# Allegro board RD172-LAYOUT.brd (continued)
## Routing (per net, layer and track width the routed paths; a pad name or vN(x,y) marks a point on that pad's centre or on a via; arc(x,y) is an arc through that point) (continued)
GND_5VAC: length 38.2
  TOP w0.2: 130,51.8 130.87,51.8
  TOP w0.25: 122.23,47 120.97,47 ; 120.63,47 v1(119.5,47)
  TOP w0.45: C82.2 130,51.8
  TOP w0.5: 113.8,45.59 113.8,45.11 113.19,44.5 IC15.4 ; 130.2,53.48 130.2,54.52 ; 130.47,54.8 v2(131.8,54.8) 131.8,54 132.7,53.1 TP55.1 ; 113.8,45.82 v2(113.8,47)
  TOP w0.6: C80.2 131,52.4 131,51.8 ; 131,51.8 131,45.54 PS10.5 ; 131,51.8 130.87,51.8
  TOP w0.8: 130.47,54.8 C81.2 130.2,54.52 ; R86.1 122.23,47 ; 120.63,47 C85.2 120.97,47 ; 113.8,45.82 R97.2 113.8,45.59 ; C80.2 130.2,53.48
  CONDUCTIVE2 w1: PS10.5 126.7,43.04 ; PS10.5 130.3,43.04 ; PS10.5 128.5,44.84
  BOTTOM w1.5: PS10.5 130.65,43.04 ; PS10.5 126.35,43.04 ; PS10.5 128.5,45.19
  vias: v2(108.1,48.4)
GND_5VDC: length 45.3
  TOP w0.2: 279.2,43.9 279.2,43.02
  TOP w0.25: v2(247.3,42.35) 247.2,43.3 247.2,44.33
  TOP w0.3: R111.2 262.7,43.85 262.4,43.55 v2(261.9,42.8)
  TOP w0.4: C96.2 261.2,43.1 261.35,43.04 v2(261.9,42.8)
  TOP w0.45: C103.2 279.2,43.9
  TOP w0.5: 249.15,42.35 v2(247.3,42.35) ; 279.2,43.02 279.2,42.9 ; 279.2,42.9 278.5,42.9 C102.2 ; 279.2,42.9 282.6,42.9 PS11.5 291.7,42.04 292,42.34 292,43.42 ; 277.32,43.8 276.27,43.8 ; IC16.4 v2(261.9,42.8) ; 276,43.52 v2(276,42.2) ; 292.27,43.7 296.2,43.7 TP64.1 ; 275.73,43.8 274.68,43.8
  TOP w0.8: 276.27,43.8 C101.2 ; C101.2 275.73,43.8 ; C101.2 276,43.52 ; C102.2 277.32,43.8 ; 274.68,43.8 C90.2 ; 292,43.42 R129.1 292.27,43.7 ; 247.2,44.33 R127.2
  TOP w1.5: IC18.4 249.15,42.35
  BOTTOM w1: PS11.5 285.4,42.04 ; PS11.5 281.6,42.04 ; PS11.5 283.5,43.94
GND_24V: length 109.4
  TOP w0.5: TP53.1 88.6,9.5 ; TP53.1 90.2,7.55 ; TP53.1 90.2,11.45 ; TP53.1 91.8,9.5 ; 69.6,16.65 C10.2 68.2,15.5 ; v2(103.9,158.8) 104.3,159.2 ; 104.3,159.2 C4.2 ; 104.3,159.2 104.25,159.2 ; C76.2 92.5,13.8 ; C76.2 88.2,13.8 ; C76.2 v2(90.2,11.9) ; TP9.1 116.7,159.5 ; TP9.1 118.3,157.55 ; TP9.1 118.3,161.45 ; 91.91,161.55 v2(90.8,161.55) ; C4.2 105.4,160.35 ; C4.2 105.4,158.05 ; LED1.C 71.2,9.65 ; 97.57,161.5 v2(98.8,161.5)
  TOP w0.6: 85.3,9.4 83.5,9.4 ; 83.5,9.4 83.5,7.8 ; 83.5,9.4 81.5,9.4 ; 83.5,9.4 C11.2 ; ZD1.A 79.4,10.85 ; ZD1.A 74.7,10.85 ; ZD1.A 76.9,8.8
  TOP w0.8: Q2.S 91.91,161.55 ; v2(130,157) 129.4,156.4 129.4,155.65 ; R17.1 97.57,161.5
  TOP w1: C50.2 129.4,152.82 130.02,152.2 PS7.2 ; PS3.2 234.19,34.9 231.17,34.9 ; PS1.3 79.46,37.25 ; PS1.3 81.61,35.1 ; PS1.3 79.46,32.95 ; PS1.3 77.31,35.1 ; C17.2 v2(227.7,34.9)
  TOP w1.2: C50.2 129.4,155.65 ; C17.2 231.17,34.9
  CONDUCTIVE2 w0.8: PS1.3 81.41,35.1 ; PS1.3 79.46,37.05 ; PS1.3 79.46,33.15 ; PS1.3 77.51,35.1
  CONDUCTIVE2 w1: PS5.2 141,35.42 ; PS5.2 142.5,34.2 ; PS5.2 144.5,35.42 ; PS9.-VIN 103.7,14.11 ; PS9.-VIN 102,12.41 ; PS9.-VIN 100.3,14.11 ; PS9.-VIN 102,15.31
  CONDUCTIVE2 w1.5: 236.95,35.42 PS3.2 233.05,35.42
  BOTTOM w1: 236.8,35.42 PS3.2 233.2,35.42 ; 130.02,151.4 PS7.2 130.02,147.8 ; PS1.3 79.46,37.25 ; 144.3,35.42 PS5.2 140.7,35.42
  BOTTOM w1.5: PS1.3 79.46,32.7 ; PS1.3 81.86,35.1 ; PS1.3 77.06,35.1
  vias: v2(4.9,143.8) v2(5,100.5) v2(5,68.6) v2(5.4,32) v2(34.8,5.6) v2(38.5,158.8) v2(53.3,17.6) v2(62.7,6.7) v2(69.1,17.1) v2(71.34,8.9) v2(76.87,8.57) v2(77.8,159.1) v2(80.4,157) v2(80.5,161.2) v2(83.5,7.72) v2(90.24,7.08) v2(111.5,11.5) v2(111.5,9) v2(111.5,6.5) v2(111.5,4) v2(116,161) v2(117.3,155.1) v2(138,28.5) v2(139,29.5) v2(139,27.4)
GND_M: length 132.6
  TOP w0.25: D20.A 203.6,142.5 203.3,142.2 203.3,141.3 203.6,141 204.08,141 ; 182.84,142.8 182.2,142.8 182,142.6 182,141.9 182.5,141.4 182.98,141.4
  TOP w0.5: 208.94,147.11 208.94,146.66 v2(209.6,146) 209.6,145.2 209.9,144.9 ; IC10.8 189.52,147.75 ; IC10.8 188.44,149.47 ; IC10.8 188.44,146.03 ; 148,144.75 C51.2 146,146.1 ; 200.06,149.47 IC12.1 198.98,147.75 ; 179.56,146.85 v2(179.56,146.1) 179.56,146.03 ; 162.35,148.1 C53.2 161.2,149.25 ; 200.06,146.85 v2(200.06,146.1) 200.06,146.03 ; IC10.3 182.09,149.47 ; C52.2 151.5,144.55 ; 203.4,137.1 R74.2 C68.1 ; 203.4,137.1 203.58,137.2 v2(204.1,137.5) v2(204.1,139.5) 204.2,140.09 204.2,140.72 ; 203.4,137.1 203.95,137.1 ; 202.59,146.89 v2(202.59,145.95) 202.59,145.31 203.4,144.5 C67.2 203.6,145.65 ; 183,141.13 v2(183,139.9) ; 209.9,144.9 C66.2 211.25,143.5 ; 209.9,144.9 209.9,145.5 ; 183.1,136.6 182.2,135.7 C59.2 R67.1 182.85,137.3 ; C58.2 182.09,145.31 v2(182.09,145.9) 182.09,146.87 ; 178.48,147.75 IC10.1 179.56,149.47 ; C68.1 202.9,135.7 203.7,135.7 204.1,136.1 v2(204.1,136.3) ; C68.1 202.8,134.45 ; IC12.3 202.59,149.47 ; 210.02,147.75 IC12.8 208.94,149.47 ; 190.2,143.7 C57.2 189.1,145.7 ; D18.A 182.84,142.8 ; R60.1 153.1,143.8
  TOP w0.6: IC12.3 202.59,146.89 ; IC12.8 208.94,147.11 ; IC9.3 161.5,149.63 ; IC12.1 200.06,146.85 ; IC9.4 161.5,150.91 ; IC10.3 182.09,146.87 ; IC10.1 179.56,146.85
  TOP w0.8: 204.2,140.72 C69.2 204.08,141 ; 182.98,141.4 C60.2 183,141.13
  TOP w1: 213.65,134.9 212.45,133.7 Q8.S ; Q8.S 212.45,131.1 ; Q8.S 214.6,133 ; 137.64,151.4 PS7.5 137.64,147.8 ; 192.4,135.05 190.95,133.6 Q7.S ; Q7.S 193.1,133 ; Q7.S 190.95,131.2
  CONDUCTIVE2 w1: 137.64,151.3 PS7.5 137.64,147.9 ; Q8.S 212.45,135.05 ; Q8.S 212.45,130.95 ; Q8.S 214.5,133 ; Q8.S 210.4,133 ; Q7.S 190.95,130.95 ; Q7.S 190.95,135.05 ; Q7.S 193,133 ; Q7.S 188.9,133
  BOTTOM w0.5: 197.75,139.35 CN6.G1 199.55,137.8 ; 179.05,135.7 CN5.G1 177.25,137.25 ; CN5.G2 173.75,134.15 ; CN5.G2 173.75,137.25 ; CN5.G2 171.95,135.7 ; TP37.1 195,142.95 ; TP37.1 196.6,141 ; TP37.1 193.4,141
  BOTTOM w1: 137.64,147.8 PS7.5 137.64,151.4
  BOTTOM w1.5: Q7.S 188.8,135.15
  vias: v2(146,144.1) v2(147.7,150.9) v2(151.5,144.1) v2(152,150) v2(161.5,149.5) v2(162,136) v2(162.1,138.6) v2(175,148.5) v2(183.1,138.5) v2(183.3,137.2) v2(189.1,146.05) v2(192.5,149) v2(211.5,149.5) v2(215,140) v2(215.5,131.5) v3(175.5,136.5) v3(196,138.6)
GND_N: length 129.8
  TOP w0.2: 177.4,54.9 178.6,54.9
  TOP w0.4: C39.2 177.3,56.6
  TOP w0.5: C42.2 164.95,49 ; C42.2 163.8,47.85 ; C42.2 163.8,50.15 ; 166.4,59.4 R49.2 C43.1 ; IC7.3 163.41,47.47 ; 154.92,61.3 IC6.4 156.63,62.38 ; 158.1,60.34 159,60.34 ; 158.1,60.34 158.1,61.3 ; 158.1,60.34 157.8,60.03 157.28,60.03 ; 159,60.34 v2(159,61.3) 158.1,61.3 ; 159,60.34 C38.2 160.2,59.2 ; 157.53,61.3 158.1,61.3 ; 184.41,46.39 184.41,46.9 v2(184.5,47.6) 184.5,48.78 ; IC5.3 184.41,44.02 ; 165.94,47.47 IC7.1 167.02,45.74 ; C43.1 168,62.2 ; C43.1 v2(166.5,61) ; C41.2 157.6,51.8 ; C41.2 156.25,49.8 ; C41.2 157.6,48.8 v2(156.42,47.68) 157.06,47 157.06,46.39 ; 146.22,56.2 v2(147.4,56.2) ; C36.2 145.4,55 ; C36.2 145.4,51 ; C36.2 146.75,53 ; C37.2 146,55.05 ; IC5.1 186.94,43.8 ; R46.1 155.35,63.2 ; R46.1 154.2,64.35 ; R46.1 154.2,62.05 ; 186.94,46.64 v1(186.94,47.3) 186.94,47.47 ; 178.06,44.02 IC5.8 178.06,47.47 ; v1(187,62.3) 186.5,61.8 C34.2 R42.1 v2(186.5,58.7) ; C32.2 176.95,49.8 ; C32.2 178.3,48.3 177.6,47.6 ; C32.2 178.3,51.8 ; IC7.2 164.68,47.47 ; 178.6,54.9 D13.A ; IC7.8 155.98,45.74
  TOP w0.6: IC5.3 184.41,46.39 ; C33.2 184.5,50.1 ; IC7.8 157.06,46.39 ; IC5.1 186.94,46.64 ; IC6.3 157.28,60.03 ; IC6.4 157.53,61.3
  TOP w0.7: Q6.S2 166.87,62.2 ; Q6.S1 165.59,62.1 ; Q6.S3 168.13,62.2
  TOP w0.8: C33.2 184.5,48.78 ; C37.2 146.22,56.2
  TOP w1: v2(166.5,59.5) 166.5,56.5 ; Q5.S 178.05,62.85 ; Q5.S 178.05,66.4 ; Q5.S 175.9,64.5 ; 140.7,43.04 141.1,43.04
  TOP w1.5: 144.55,43.04 PS5.5 141.1,43.04
  CONDUCTIVE2 w1: Q5.S 178.05,66.55 ; Q5.S 176,64.5 ; Q5.S 180.1,64.5 ; Q5.S 178.05,62.45 ; PS5.5 141.3,43.04 ; PS5.5 142.5,44.24 ; PS5.5 144.2,43.04
  BOTTOM w0.5: TP28.1 155.4,62.9 ; TP28.1 157,60.95 ; TP28.1 157,64.85 ; TP28.1 158.6,62.9 ; CN3.G1 180.25,57.2 ; 179.25,59.4 CN4.G2 177.45,57.85 ; CN4.G1 173.95,57.85
  BOTTOM w1: 144.6,43.04 PS5.5 140.7,43.04 ; Q5.S 178.05,66.9 ; Q5.S 180.3,64.5 ; Q5.S 175.8,64.5 ; Q5.S 178.05,62.4
  vias: v1(176.5,55.4) v2(162.5,63.3) v2(162.5,61.9) v2(162.5,60.5) v2(162.5,59.1) v2(164,60.1) v2(164.1,63.3) v2(164.1,61.8) v2(164.68,47.6) v2(164.8,59) v2(165.2,60.8) v2(165.9,56.5) v2(175.7,51.2) v2(175.75,53.75) v2(177.7,47.6) v3(175.7,58.6) v3(183.8,56.4)
GND_P: length 128.3
  TOP w0.2: 206.5,55.1 207.82,55.1
  TOP w0.5: v2(203.3,47.9) 203.6,48.5 C15.2 ; IC3.1 202.02,45.74 ; IC3.1 200.94,47.47 ; IC3.1 200.94,44.02 ; 203.56,44.02 IC1.8 202.48,45.74 ; 209.91,46.65 v2(209.91,47.6) 209.9,48.9 209.8,49 209.8,49.98 ; 198.41,47.8 IC3.3 198.41,44.02 ; 199,66.15 C26.1 197.85,65 ; 207.82,55.1 D8.A ; Q4.S1 195.37,68.03 ; C24.2 194.1,53.5 ; C24.2 192.9,51.5 ; C24.2 194.1,49.5 ; C18.2 230.5,42.25 ; C18.2 228.5,43.6 ; C18.2 232.5,43.6 ; C20.2 205.2,56.7 v3(205,56.9) ; 225.7,56.55 C21.2 v2(221.69,55.4) 221.69,54.3 ; C15.2 202.25,50.5 ; C15.2 203.6,52.5 ; 197.8,47.6 C25.2 198.95,49 ; 227.6,43.55 C19.2 228.5,44.7 ; 215.8,60.92 215.8,59.88 ; 212.44,47.47 v1(212.44,47.3) IC1.1 ; 199.68,47.9 IC3.2 199.68,44.02 ; C22.2 215.8,61.7 v2(216.2,62.5) ; IC1.3 209.91,44.02 ; IC2.3 225.06,51.62 ; IC2.4 223.79,51.62 ; IC2.4 222.72,53.34 ; IC2.4 223.79,55.05 ; R30.2 197.85,63.5 ; 224.85,44.7 R27.1 226,43.55 ; C16.2 209.8,51.15 ; 215.8,59.58 215.8,58.6
  TOP w0.6: v2(191.9,47.7) 192.06,46.9 IC3.8 ; v2(203.3,47.9) 203.56,47.65 IC1.8 ; IC1.3 209.91,46.65
  TOP w0.7: Q4.S1 196.5,66.4 ; Q4.S3 199.03,66.4 ; 197.76,68.03 197.76,66.2
  TOP w0.8: 215.8,59.88 R26.1 215.8,59.58 ; C16.2 209.8,49.98 ; C22.2 215.8,60.92
  TOP w1: Q3.S 207.05,62.6 ; v2(196.7,59.7) v2(196.7,62.6)
  TOP w1.5: 233.3,43.04 PS3.5 237.05,43.04
  CONDUCTIVE2 w1: Q3.S 207.05,66.55 ; Q3.S 209.1,64.5 ; Q3.S 207.05,62.45 ; Q3.S 205,64.5 ; PS3.5 233.3,43.04 ; PS3.5 236.7,43.04 ; PS3.5 235,44.24
  BOTTOM w0.5: 222.3,56.95 CN1.G1 223.85,58.75 ; 206.75,59.25 CN2.G2 208.55,57.7 ; CN1.G2 223.85,62.25
  BOTTOM w0.7: 207,72.25 207,75.07
  BOTTOM w1: Q3.S 207.05,67.1 ; Q3.S 207.05,62.25 ; Q3.S 204.8,64.5 ; Q3.S 209.3,64.5
  BOTTOM w1.5: 232.9,43.04 PS3.5 236.7,43.04
  BOTTOM w1.7: 207,75.07 TP19.1
  vias: v2(194.4,67.8) v2(194.5,66.3) v2(195.7,65.5) v2(195.9,64) v2(196.8,66.4) v2(197.6,65.1) v2(197.6,63.5) v2(198.4,66.4) v2(199.7,47.7) v2(215.2,58.3) v2(227.7,42.2) v3(223.1,60.5)
/DI0_BO: length 40.6
  TOP w0.2: 236.25,6.02 236.25,4.73 v1(236.4,4.4) ; v1(236.4,14.7) 236,15.1 230.45,15.1 229.25,16.3 216.7,16.3 215.6,17.4 209.95,17.4
  TOP w0.25: CN8.51 236.25,6.02
  TOP w0.8: 209.95,17.4 R139.2
  BOTTOM w0.2: v1(236.4,4.4) v1(236.4,14.7)
/DI1_BO: length 25.2
  TOP w0.2: 236.25,11.98 236.25,13.35 234.95,14.65 230.26,14.65 229.11,15.8 216.2,15.8 215.6,16.4 214.75,16.4
  TOP w0.25: CN8.52 236.25,11.98
  TOP w0.8: 214.75,16.4 R140.2
/DO1_BI: length 66.4
  TOP w0.2: v1(237.9,15.3) 245.7,15.3 251.2,9.8 264.04,9.8 274.24,20 285.55,20 ; 287.57,17.27 286.85,17.27 285.7,18.43 285.7,19.85 ; 233.75,11.98 v1(233.75,12.8)
  TOP w0.25: CN8.42 233.75,11.98
  TOP w0.35: IC20.2 287.57,17.27
  TOP w0.8: 285.55,20 R141.1 285.7,19.85
  BOTTOM w0.2: v1(237.9,15.3) 237.6,15.5 235.4,15.5 233.75,13.85 v1(233.75,12.8)
/DO3_BI: length 75.4
  TOP w0.2: v1(183.8,15.3) 228.97,15.3 230.07,14.2 233.6,14.2 234.4,13.4 234.4,12.5 234.25,12.35 234.25,11.98 ; 186.57,18.68 v1(183.8,18.68) 183.22,18.68 181.9,17.35 181.9,16.55 181.1,15.75 178.05,15.75 177.7,16.1 177.7,20 176.1,21.6 175.35,21.6
  TOP w0.25: 234.25,11.98 CN8.44
  TOP w0.35: IC19.6 186.57,18.68
  TOP w0.8: 175.35,21.6 R133.1
  BOTTOM w0.2: v1(183.8,15.3) v1(183.8,18.68)
/FLT: length 510
  TOP w0.2: 195.25,28.55 195.25,28.35 ; 195.25,28.55 195.05,28.35 ; 195.25,28.55 195.45,28.35 ; 195.25,28.55 195.25,32.35 197.13,34.23 197.13,35.48 ; 195.25,28.35 195.05,28.35 ; 195.25,28.35 195.45,28.35 ; 183.55,28.35 183.75,28.35 ; 183.55,28.35 170.35,28.35 170.3,28.4 v1(170,28.6) 169.7,28.4 169.65,28.35 163.25,28.35 162.74,28.86 162.74,32.1 162.13,32.7 162.13,35.48 ; 183.55,28.35 183.75,28.55 ; 183.75,28.35 183.75,28.55 ; 183.75,28.35 183.95,28.35 ; 183.37,158.02 v1(183.37,159.5) ; 170.5,20.77 170.5,19.3 171.3,18.5 171.3,15 172.2,14.1 174.9,14.1 175.2,14.4 175.2,15.05 ; 183.75,28.55 183.75,34.15 183.13,34.77 183.13,35.48 ; 183.75,28.55 183.95,28.35 ; 195.05,28.35 183.95,28.35 ; 175.29,16.8 176.35,16.8 176.7,16.45 176.7,15.5 177.25,14.95 181.75,14.95 184.18,17.38 186.57,17.38 ; 195.45,28.35 207.23,28.35 v1(207.8,28.92) 207.8,34.1 208.63,34.94 208.63,35.48 ; v1(208.4,22.8) 222.49,22.8 226.54,18.75 246.79,18.75 253.94,11.6 263.01,11.6 275.26,23.85 290.56,23.85 295,28.29 v1(295,29.5) ; v1(203.87,159.25) 203.87,158.02
  TOP w0.3: v1(170.5,22.6) 170.5,21.25 ; 175.2,16.61 175.2,15.39
  TOP w0.6: 203.87,158.02 IC12.13 ; 162.13,35.48 IC7.13 ; 183.13,35.48 IC5.13 ; IC10.13 183.37,158.02 ; 208.63,35.48 IC1.13 ; IC3.13 197.13,35.48
  TOP w0.8: 175.2,15.39 R135.1 175.2,15.05 ; 175.29,16.8 C108.1 175.2,16.61
  TOP w1.7: 170.5,21.25 TP67.1 170.5,20.77
  BOTTOM w0.2: v1(295,29.5) 295,31.79 305.3,42.09 305.3,112.55 310.45,117.7 318.41,117.7 323.8,123.09 323.8,152.71 314.56,161.95 218.95,161.95 215.6,158.6 204.51,158.6 v1(203.87,159.25) 203.57,159.45 202.25,159.45 201.55,158.75 184.12,158.75 v1(183.37,159.5) ; v1(170,28.6) 170.5,28.1 v1(170.5,22.6) ; v1(207.8,28.92) 207.8,23.4 v1(208.4,22.8)
/MAINRLY_24V: length 23.8
  TOP w0.5: 100.33,159.4 94.4,159.4 94.35,159.45 93.07,159.45 ; 85,160.15 85,156.35 85.6,155.75 RLY2.1 89.62,156.92 92.15,159.45 92.72,159.45 ; 100.65,161.12 100.65,160.4 100.6,159.93
  TOP w0.8: 92.72,159.45 Q2.D 93.07,159.45 ; 100.6,159.93 R12.2 100.33,159.4 ; 100.65,161.12 D2.A
  TOP w1.7: 85,160.15 TP11.1
/PWM1A_BI: length 69.5
  TOP w0.2: 229.75,6.02 229.75,5.45 230.2,5 230.2,3.85 228.9,2.55 223.85,2.55 216.95,9.45 v1(186.5,9.45) ; 180.55,21.6 181.5,21.6 181.8,21.3 v1(185.35,21.3) 185.71,21.27 186.57,21.27
  TOP w0.25: 229.75,6.02 CN8.25
  TOP w0.35: IC19.2 186.57,21.27
  TOP w0.8: 180.55,21.6 R136.1
  BOTTOM w0.2: v1(186.5,9.45) 186.5,20.15 v1(185.35,21.3)
/PWM1B_BI: length 63.8
  TOP w0.2: 186.57,20.62 182.07,20.62 v1(181.7,20.25) 181.45,20 180.55,20 ; 229.75,11.98 229.75,13.25 228.7,14.3 184.6,14.3 184.3,14 182.1,14 182,14.1 v1(181.7,14.3)
  TOP w0.25: 229.75,11.98 CN8.26
  TOP w0.35: IC19.3 186.57,20.62
  TOP w0.8: 180.55,20 R130.1
  BOTTOM w0.2: v1(181.7,20.25) v1(181.7,14.3)
/PWM2A_BI: length 71.7
  TOP w0.2: 230.25,6.02 230.25,5.65 230.7,5.2 230.7,3.65 229.15,2.1 223.4,2.1 217,8.5 186.1,8.5 185.6,9 v1(184.45,9) ; 186.57,19.98 v1(184,19.98) 182.57,19.98 181,18.4 180.55,18.4
  TOP w0.25: 230.25,6.02 CN8.27
  TOP w0.35: IC19.4 186.57,19.98
  TOP w0.8: 180.55,18.4 R131.1
  BOTTOM w0.2: v1(184.45,9) 184.45,19.52 v1(184,19.98)
/PWM2B_BI: length 63.3
  TOP w0.2: 230.25,11.98 230.25,13.39 228.84,14.8 184.4,14.8 184.2,14.6 183.36,14.6 v1(183,14.65) ; 180.55,16.8 181.2,16.8 181.45,17.05 181.45,17.85 v1(182.85,19.25) 183.45,19.32 186.57,19.32
  TOP w0.25: CN8.28 230.25,11.98
  TOP w0.35: IC19.5 186.57,19.32
  TOP w0.8: 180.55,16.8 R132.1
  BOTTOM w0.2: v1(183,14.65) 183,16.15 183.3,16.45 183.3,17.95 182.85,18.4 v1(182.85,19.25)
/PWM_MA: length 407.1
  TOP w0.2: 193.72,161.5 195.7,161.5 197.6,163.4 211.2,163.4 211.7,162.9 211.7,160.4 212.1,160 219.5,160 221.2,161.7 314.03,161.7 323.2,152.53 323.2,123.2 318.2,118.2 310.2,118.2 305.2,113.2 305.2,37.08 291.07,22.95 275.77,22.95 263.52,10.7 251.64,10.7 245.84,16.5 231.03,16.5 229.73,17.8 217.3,17.8 215.6,19.5 207,19.5 206.2,18.7 196.1,18.7 194.82,19.98 193.43,19.98 ; 185.5,160.05 185.5,159.16 185.91,158.75 185.91,157.96 ; 185.52,160.2 186,160.2 186.5,160.7 186.5,162.6 186.8,162.9 190.1,162.9 191.5,161.5 TP69.1
  TOP w0.35: IC19.17 193.43,19.98
  TOP w0.6: IC10.11 185.91,157.96
  TOP w0.8: 185.5,160.05 R62.1 185.52,160.2
  TOP w1.7: 193.72,161.5 TP69.1
/PWM_MB: length 385.8
  TOP w0.2: v1(205.1,160.4) 205.45,160.33 205.67,160.33 206.08,159.92 R72.1 ; 213.72,161.5 v1(215.7,161.5) 220.1,161.5 220.8,162.2 314.16,162.2 323.8,152.56 323.8,123.09 318.41,117.7 310.41,117.7 305.7,112.99 305.7,36.87 291.33,22.5 276.03,22.5 263.78,10.25 251.39,10.25 245.64,16 230.82,16 229.52,17.3 217.1,17.3 215.4,19 207.2,19 206.4,18.2 195.9,18.2 194.78,19.32 193.43,19.32 ; 206.41,157.99 206.41,158.8 206.5,158.9 206.5,159.55
  TOP w0.35: 193.43,19.32 IC19.16
  TOP w0.6: IC12.11 206.41,157.99
  TOP w0.8: 206.5,159.55 R72.1
  TOP w1.7: 213.72,161.5 TP70.1
  BOTTOM w0.2: v1(205.1,160.4) 206.75,161.5 v1(215.7,161.5)
/PWM_N: length 124.6
  TOP w0.2: R38.1 181.95,31.7 182.45,31.2 v1(182.45,29.55) ; 241.97,14 238,14 236.45,15.55 230.63,15.55 229.38,16.8 216.9,16.8 215.2,18.5 207.38,18.5 206.57,17.7 198.75,17.7 v1(198.53,17.48) 195.93,17.48 194.72,18.68 193.43,18.68 ; v1(161.2,29.9) 161.2,31.3 160.6,31.9 159.62,31.9 ; R47.1 159.59,32.6 159.59,35.48 ; v1(198.98,24.14) 198.5,24.3 185.3,24.3 184.6,23.6 v1(182.2,23.6) 181.9,23.9 162.8,23.9 162.5,24.2 v1(161.2,24.2) ; 180.59,35.48 180.59,33.05 181.2,32.45 181.2,31.85
  TOP w0.35: IC19.15 193.43,18.68
  TOP w0.6: IC7.11 159.59,35.48 ; IC5.11 180.59,35.48
  TOP w0.8: 181.2,31.85 R38.1 ; R47.1 159.62,31.9
  TOP w1.7: 241.97,14 TP71.1
  BOTTOM w0.2: v1(161.2,29.9) v1(161.2,24.2) ; v1(182.2,23.6) 182.2,29.3 v1(182.45,29.55) ; v1(198.53,17.48) 198.98,17.93 v1(198.98,24.14)
/PWM_P: length 48.9
  TOP w0.2: v1(206.2,30.45) 206.2,31.35 205.85,31.7 R19.1 ; 192.38,20.62 191.7,20.62 191.4,20.93 191.4,22.6 191.7,22.9 v1(192.8,22.9) 194.5,22.9 194.9,23.3 198.1,23.3 199.4,22 201.18,22 ; 192.8,31.85 192.8,32.69 194.59,34.48 194.59,35.48 ; R28.1 193.6,31.7 193.95,31.35 v1(193.95,29.6) ; v1(203.8,22) 201.62,22
  TOP w0.25: 206.09,35.46 206.09,33.9 204.9,32.7 204.9,31.87
  TOP w0.35: IC19.18 192.38,20.62
  TOP w0.6: IC3.11 194.59,35.48 ; IC1.11 206.09,35.46
  TOP w0.8: 204.9,31.87 R19.1 ; 192.8,31.85 R28.1
  TOP w1.7: 201.18,22 TP68.1 201.62,22
  BOTTOM w0.2: v1(193.95,29.6) 193.95,25.05 192.8,23.9 v1(192.8,22.9) ; v1(206.2,30.45) 206.2,24.4 v1(203.8,22)
/RESET: length 502.4
  TOP w0.2: v1(199.55,17) 199.25,16.8 195.9,16.8 194.68,18.02 193.43,18.02 ; v1(294,29.5) 294,28 290.3,24.3 275,24.3 262.75,12.05 254.12,12.05 246.97,19.2 226.8,19.2 222.19,23.8 208.5,23.8 ; 209.91,35.61 209.91,35.01 208.41,33.51 v1(208.41,30.45) ; 182.09,158.02 v1(182.09,158.8) ; 206.32,23.8 204.2,23.8 203.6,24.4 v1(200,24.4) 199.7,24.8 184.6,24.8 v1(184.1,24.3) 183,24.3 182.7,24.6 v1(163.5,24.6) ; v1(163.5,29.1) 163.41,29.7 163.41,35.48 ; v1(195.91,30.45) 198.41,32.95 198.41,35.48 ; 184.41,35.48 v1(184.41,30.3) ; v1(202.59,158.8) 202.59,158.02 ; v1(208.5,23.8) 206.62,23.8
  TOP w0.35: 193.43,18.02 IC19.14
  TOP w0.6: 202.59,158.02 IC12.14 ; IC10.14 182.09,158.02 ; IC5.14 184.41,35.48 ; IC1.14 209.91,35.61 ; IC7.14 163.41,35.48 ; IC3.14 198.41,35.48
  TOP w1.7: 206.32,23.8 TP72.1 206.62,23.8
  BOTTOM w0.2: v1(195.91,30.45) 195.91,26.09 196.5,25.5 198.9,25.5 v1(200,24.4) 199.55,23.95 v1(199.55,17) ; v1(182.09,158.8) 182.6,158.29 202.09,158.29 v1(202.59,158.8) 203.9,157.5 217.5,157.5 221.5,161.5 314.3,161.5 323.3,152.5 323.3,123.3 318.2,118.2 310.2,118.2 304.8,112.8 304.8,42.3 294,31.5 v1(294,29.5) ; v1(208.41,30.45) 208.41,29.6 208.5,29.5 v1(208.5,23.8) ; v1(163.5,29.1) v1(163.5,24.6) ; v1(184.1,24.3) 184.1,30 v1(184.41,30.3)
AC_L: length 101.5
  TOP w1: RLY2.3 117.1,143.75 117.69,143.84 TP2.1
  CONDUCTIVE2 w1: R5.2 116.5,120.2 ; R5.2 118.3,122 ; R5.2 116.5,123.8 ; R5.2 114.7,122 ; R4.2 114.7,133 ; R4.2 118.3,133 ; R4.2 116.5,134.8 ; R4.2 116.5,131.2 ; 152.6,138.15 151.5,139.25 C6.1 ; D7.A 162.56,122.43 ; D7.A 164.46,120.4 ; D7.A 164.46,124.6 ; C7.1 129.2,139.25 ; C7.1 131,140.9 ; C7.1 132.8,139.25 ; C7.1 131,137.45 ; 162.56,113.57 D12.C 164.46,115.47 ; C6.1 149.2,139.25 ; C6.1 151,137.45
  CONDUCTIVE2 w1.5: RLY2.3 114.8,141.5 ; RLY2.3 117.05,143.75 ; RLY2.3 114.8,145.5 ; RLY2.3 112.55,143.75
  BOTTOM w1: R4.2 115,133 ; R4.2 116.5,131.1 ; R4.2 118.4,133 ; R4.2 116.5,134.9 ; 153.4,137.95 153.4,138.3 152.45,139.25 C6.1 ; 164.46,124.03 D7.A 164.46,120.4 ; 164.46,111.47 D12.C 164.46,115.2 ; R5.2 116.5,120.1 ; R5.2 116.5,123.9 ; R5.2 118.4,122 ; R5.2 115,122 ; C7.1 131,141
  BOTTOM w1.5: RLY2.3 112.45,143.75 ; RLY2.3 114.8,145.6 ; RLY2.3 117.15,143.75 ; RLY2.3 114.8,141.4 ; D12.C 162.5,113.57 ; C7.1 133.5,139.25 ; C7.1 131,136.75 ; C7.1 128.5,139.25 ; 148.5,139.25 C6.1 151,136.75 ; D7.A 162.36,122.43
AC_L_IN: length 132.1
  TOP w0.25: v1(103.9,73.3) 103.9,68.5 R88.1
  TOP w0.5: 40.65,15 39.1,15 33.74,20.36 PS1.2
  TOP w1.7: 40.65,15 TP10.1
  CONDUCTIVE2 w1: R1.1 95.2,133 ; R1.1 97,134.8 ; R1.1 98.8,133 ; R1.1 97,131.2 ; R2.1 97,123.8 ; R2.1 97,120.2 ; R2.1 98.8,122 ; R2.1 95.2,122 ; C3.1 101.25,95.2 ; C3.1 99.45,97 ; C3.1 101.25,98.8 ; C3.1 103.05,97 ; C120.1 65.5,89 ; C120.1 68.7,89 ; C120.1 67,87.3 ; C120.1 67,90.7 ; PS1.2 33.74,26.99 ; PS1.2 33.74,22.89 ; PS1.2 31.69,24.94 ; PS1.2 35.79,24.94
  CONDUCTIVE2 w1.5: RLY2.4 87.2,145.5 ; RLY2.4 89.45,143.75 ; RLY2.4 84.95,143.75 ; RLY2.4 87.2,141.5
  CONDUCTIVE2 w2: L2.2 93.2,124.5
  BOTTOM w1: PS1.2 31.59,24.94 ; PS1.2 33.74,27.09 ; PS1.2 35.89,24.94 ; PS1.2 33.74,22.79 ; C120.1 65.5,89 ; C120.1 67,90.8 ; C120.1 67,87.2 ; C120.1 68.8,89 ; R2.1 97,120.1 ; R2.1 97,123.9 ; R2.1 95.1,122 ; R2.1 98.6,122 ; R1.1 95.1,133 ; R1.1 97,134.9 ; R1.1 98.6,133 ; R1.1 97,131.1 ; C3.1 101.25,99.5 ; C3.1 103.75,97 ; C3.1 98.75,97 ; C3.1 101.25,94.5
  BOTTOM w1.5: RLY2.4 89.55,143.75 ; RLY2.4 84.85,143.75 ; RLY2.4 87.2,145.5 ; RLY2.4 87.2,141.4 ; L2.2 87.5,124.5 ; L2.2 92.65,124.5 ; L2.2 90,127.15 ; L2.2 90,121.85
AC_N: length 95
  TOP w0.25: 116.3,51.56 116.3,52.3 116,52.6 116,53.08 ; 115.83,54.8 v1(114.7,54.8) ; 116.15,51.33 114.72,51.33 114.4,51 114.4,50.37 ; 116,53.37 116,54.63
  TOP w0.45: R100.1 114.4,50.37
  TOP w0.6: 116.3,51.56 L5.2 116.15,51.33
  TOP w0.8: 116,53.37 R94.1 116,53.08 ; 116,54.63 C87.2 115.83,54.8
  CONDUCTIVE2 w0.25: CT1.10 99.85,72.55 108,64.4 108,57.5 109.1,56.4 113.8,56.4 114.7,55.5 v1(114.7,54.8)
  CONDUCTIVE3 w1.2: 97.75,77.29 CT1.9 102.4,77.29 ; CT1.8 101.9,79.83 ; CT1.8 99.85,81.55 ; CT1.8 97.6,79.83 ; 99.85,73.05 CT1.10 98.05,74.75
  CONDUCTIVE3 w2: L3.1 126.45,82.7 126.25,82.9 ; L3.1 129.4,78.6 ; L3.1 132.35,82.7 132.55,82.9 ; L3.1 129.4,87.2
  BOTTOM w1.2: CT1.8 97.75,79.83 ; CT1.8 99.85,81.6 ; CT1.8 102.25,79.83 ; 97.75,77.29 CT1.9 101.85,77.29 ; 97.75,74.75 CT1.10 99.85,73.15
  BOTTOM w2: L3.1 129.4,78.4 ; L3.1 126.25,82.7 ; L3.1 129.4,87.3 ; L3.1 132.55,82.7
AC_N_IN: length 134.9
  TOP w0.5: TP8.1 30.9,53.2 ; TP8.1 32.5,55.15 ; TP8.1 34.1,53.2 ; 33.74,47.41 33.74,49.35 32.5,50.59 32.5,52.85
  TOP w1: PS1.1 33.74,43.11 ; PS1.1 35.89,45.26 ; PS1.1 33.74,47.41 ; PS1.1 31.59,45.26 ; CT1.3 87.15,81.83 ; CT1.3 85.15,79.83 ; CT1.3 89,79.83 ; CT1.1 89,74.75 ; CT1.1 87.15,73.25 ; CT1.1 85.15,74.75 ; C3.2 76.25,97 ; C3.2 78.75,94.5 ; C3.2 81.25,97 ; C3.2 78.75,99.5 ; C6.2 151,114.25 ; C6.2 148.5,111.75 ; C6.2 153.5,111.75 ; C6.2 151,109.1 ; 85.15,77.29 CT1.2 89,77.29 ; C7.2 131,114.25 ; C7.2 128.5,111.75 ; C7.2 131,109.75 ; C7.2 133.5,111.75 ; C121.1 78,75.8 ; C121.1 76.2,74 ; C121.1 78,72.2 ; C121.1 79.8,74
  TOP w1.7: 32.5,52.85 TP8.1
  TOP w2.5: L2.4 92.8,115.5
  CONDUCTIVE3 w1: CT1.3 87.15,81.73 ; CT1.3 85.25,79.83 ; CT1.3 89.05,79.83 ; 85.25,77.29 CT1.2 89.05,77.29 ; C3.2 78.75,95.2 ; C3.2 78.75,98.8 ; C3.2 80.55,97 ; C3.2 76.95,97 ; C121.1 78,75.7 ; C121.1 78,72.3 ; C121.1 79.7,74 ; C121.1 76.3,74 ; C6.2 152.8,111.75 ; C6.2 151,113.55 ; C6.2 149.2,111.75 ; C6.2 151,109.95 ; PS1.1 35.79,45.26 ; PS1.1 33.74,47.31 ; PS1.1 31.69,45.26 ; PS1.1 33.74,43.21 ; CT1.1 87.15,73.5 ; CT1.1 89.05,74.75 ; CT1.1 85.25,74.75 ; C7.2 131,113.55 ; C7.2 132.8,111.75 ; C7.2 129.2,111.75 ; C7.2 131,109.95
  CONDUCTIVE3 w1.5: L2.4 90,113.25 ; L2.4 92.25,115.5 ; L2.4 90,117.75 ; L2.4 87.75,115.5
AD0: length 66.3
  TOP w0.2: 250.32,18.8 248.2,18.8 247.35,19.65 227.62,19.65 v1(227.1,20) ; 225.75,6.02 225.75,5.43 v1(225.6,5.1) ; 263.8,16.85 263.8,13.8 262.5,12.5 255,12.5 250.4,17.1 TP58.1
  TOP w0.25: 262.54,20.16 262.54,19.76 262.9,19.4 263.4,19.4 263.8,19 263.8,18.52 ; 263.8,17.17 263.8,18.33 ; 225.75,6.02 CN8.9
  TOP w0.5: IC17.14 262.54,20.16
  TOP w0.8: 263.8,18.33 C88.2 263.8,18.52 ; 263.8,17.17 R96.2 263.8,16.85
  TOP w1.7: TP58.1 250.32,18.8
  BOTTOM w0.2: v1(225.6,5.1) 226.05,5.55 226.05,14.25 227.1,15.3 v1(227.1,20)
AD1: length 169.5
  TOP w0.2: v1(89.9,43.35) 89.5,43.75 89.5,47.27 ; v1(119.5,25) 120.36,25.25 128.56,25.25 133.61,20.2 168.6,20.2 170.8,18 170.8,14.85 172.05,13.6 184.9,13.6 187.95,10.55 195.45,10.55 198.7,13.8 225.8,13.8 226.05,13.55 226.05,12.6 225.75,12.3 225.75,11.98
  TOP w0.25: 225.75,11.98 CN8.10
  TOP w0.3: 89.5,47.77 89.5,49.35 89.9,49.75 91.76,49.75 ; IC13.9 92.5,50.2 92.05,49.75 91.76,49.75 ; 91.76,49.75 91.76,50.51
  TOP w0.5: IC13.8 91.76,50.51
  TOP w1.7: 89.5,47.77 TP47.1 89.5,47.27
  BOTTOM w0.25: v1(119.5,25) 115.7,28.8 115.7,32.15 114.05,33.8 109.15,33.8 101.2,41.75 91.5,41.75 v1(89.9,43.35)
AD2: length 164.9
  TOP w0.2: v1(120.3,24.4) 120.7,24.8 128.3,24.8 133.4,19.7 168.4,19.7 170.3,17.8 170.3,14.75 171.95,13.1 184.7,13.1 187.7,10.1 217.1,10.1 223.85,3.35 225.5,3.35 226.75,4.6 226.75,6.02
  TOP w0.25: 97.53,50 96.09,50 95.84,50.25 95.84,50.66 ; 226.75,6.02 CN8.13 ; 97.7,51.08 97.7,50.17
  TOP w0.3: TP46.1 98.4,47.9 v1(97.7,48.6) 97.7,49.81
  TOP w0.45: C70.2 97.7,51.08
  TOP w0.5: IC13.14 95.84,50.66
  TOP w0.8: 97.7,49.81 R79.2 ; R79.2 97.53,50 ; R79.2 97.7,50.17
  BOTTOM w0.25: v1(97.7,48.6) 98.15,48.15 98.15,45.6 109.45,34.3 114.25,34.3 116.2,32.35 116.2,29.1 118.4,26.9 118.7,26.9 120.3,25.3 v1(120.3,24.4)
AD4: length 69.2
  TOP w0.2: v1(227.75,3.15) 227.7,3.65 227.7,4.8 227.75,4.85 227.75,6.02 ; v1(230.6,22.9) 230.9,22.6 266.57,22.6
  TOP w0.25: CN8.17 227.75,6.02
  TOP w0.3: 264.18,24 263.1,24 262.54,24.56 262.54,25.8 ; 266,24.46 266,24 ; 266,24 264.49,24 ; 266,24 266.6,24 266.8,23.8 266.8,22.78
  TOP w0.45: C94.2 266,24.46
  TOP w0.5: 262.54,25.8 IC17.1
  TOP w0.8: 264.49,24 R108.2 264.18,24
  TOP w1.7: 266.8,22.78 TP59.1 266.57,22.6
  BOTTOM w0.2: v1(227.75,3.15) 227.85,3.7 227.85,20.15 v1(230.6,22.9)
AD6: length 56.8
  TOP w0.2: 252.72,24.6 251.7,24.6 v1(251.1,24) ; v1(231.2,17.4) 245.6,17.4 248.7,14.3 v1(249.5,14.3) ; 228.75,6.02 v1(228.75,4.1)
  TOP w0.25: CN8.21 228.75,6.02 ; 255,25.28 255,24.73
  TOP w0.3: 255,24.6 256.2,24.6 R124.2 ; 255,24.6 255,24.73 ; 255,24.6 253.07,24.6 ; 258.46,25.96 258.46,25.4 258.16,25.1 256.89,25.1
  TOP w0.45: C97.2 255,25.28
  TOP w0.5: IC17.7 258.46,25.96
  TOP w0.8: 256.89,25.1 R124.2
  TOP w1.7: 252.72,24.6 TP62.1 253.07,24.6
  BOTTOM w0.2: v1(231.2,17.4) 230.4,16.6 230.4,7.25 228.75,5.6 v1(228.75,4.1) ; v1(251.1,24) 251.1,15.9 v1(249.5,14.3)
FG: length 373.9
  TOP w1: C123.2 35.2,79 ; C123.2 37,80.8 ; C123.2 37,77.2 ; C123.2 38.8,79 ; C9.2 56,77.2 ; C9.2 54.2,79 ; C9.2 56,80.8 ; C9.2 57.8,79 ; C120.2 67,77.2 ; C120.2 68.8,79 ; C120.2 65.2,79 ; C120.2 67,80.8 ; C121.2 66.2,74 ; C121.2 68,75.8 ; C121.2 69.8,74 ; C121.2 68,72.2 ; C8.2 47.2,79 ; C8.2 49,77.2 ; C8.2 49,80.8 ; C8.2 50.8,79 ; C122.2 30,77.2 ; C122.2 30,80.8 ; C122.2 28.2,79 ; C122.2 31.8,79
  TOP w2: TB3.1 13,78.4 ; TB3.1 17,80.5 ; TB3.1 21.5,78.4 ; TB3.1 17,75.65 ; TB3.2 23.2,69.6 ; TB3.2 17,66.85 ; TB3.2 13,69.6 ; TB3.2 17,72.35 ; CAM1.1 40.3,72 ; CAM1.1 35,66.8 ; CAM1.1 28.5,72 ; CAM1.1 35,76.8
  CONDUCTIVE2 w1: C120.2 67,77.3 ; C120.2 65.3,79 ; C120.2 68.7,79 ; C120.2 67,80.7 ; C9.2 54.3,79 ; C9.2 56,80.7 ; C9.2 56,77.3 ; C9.2 57.7,79 ; C122.2 30,80.7 ; C122.2 30,77.3 ; C122.2 28.3,79 ; C122.2 31.7,79 ; C8.2 49,80.7 ; C8.2 50.7,79 ; C8.2 47.3,79 ; C8.2 49,77.3 ; C123.2 37,80.7 ; C123.2 35.3,79 ; C123.2 37,77.3 ; C123.2 38.7,79 ; C121.2 68,75.7 ; C121.2 66.3,74 ; C121.2 69.7,74 ; C121.2 68,72.3
  CONDUCTIVE2 w2: TB3.2 17,72.3 ; TB3.2 13,69.6 ; TB3.2 23.5,69.6 ; TB3.2 17,66.7 ; TB3.1 17,75.1 ; TB3.1 17,80.5 ; TB3.1 13,78.4 ; TB3.1 21.9,78.4 ; 35,67.2 CAM1.1 ; CAM1.1 39.9,72 ; CAM1.1 29.5,72 ; CAM1.1 35,76.6
  CONDUCTIVE3 w1: C8.2 47.3,79 ; C8.2 49,80.7 ; C8.2 50.7,79 ; C8.2 49,77.3 ; C122.2 31.7,79 ; C122.2 30,80.7 ; C122.2 30,77.3 ; C122.2 28.3,79 ; C9.2 56,80.7 ; C9.2 57.7,79 ; C9.2 54.3,79 ; C9.2 56,77.3 ; C123.2 38.7,79 ; C123.2 37,80.7 ; C123.2 37,77.3 ; C123.2 35.3,79 ; C120.2 68.7,79 ; C120.2 67,77.3 ; C120.2 65.3,79 ; C120.2 67,80.7 ; C121.2 69.7,74 ; C121.2 68,72.3 ; C121.2 66.3,74 ; C121.2 68,75.7
  CONDUCTIVE3 w2: TB3.2 13,69.6 ; TB3.2 22,69.6 ; TB3.2 17,72.7 ; TB3.2 17,66.9 ; 13,78.4 TB3.1 ; TB3.1 17,75.6 ; TB3.1 17,80.5 ; TB3.1 22,78.4 ; CAM1.1 35,66.7 ; CAM1.1 29.3,72 ; CAM1.1 41.3,72 ; CAM1.1 35,76.9
  BOTTOM w1: C9.2 57.8,79 ; C9.2 56,77.2 ; C9.2 56,80.8 ; C9.2 54.2,79 ; C123.2 37,80.8 ; C123.2 35.2,79 ; C123.2 38.8,79 ; C123.2 37,77.2 ; C120.2 68.8,79 ; C120.2 67,77.2 ; C120.2 67,80.8 ; C120.2 65.2,79 ; C8.2 49,80.8 ; C8.2 50.8,79 ; C8.2 49,77.2 ; C8.2 47.2,79 ; C122.2 28.2,79 ; C122.2 30,77.2 ; C122.2 31.8,79 ; C122.2 30,80.8 ; C121.2 66.2,74 ; C121.2 68,72.2 ; C121.2 69.8,74 ; C121.2 68,75.8
  BOTTOM w2: CAM1.1 35,77 ; CAM1.1 28.6,72 ; CAM1.1 35,66.6 ; CAM1.1 40.7,72 ; 13,69.6 TB3.2 ; TB3.2 17,66.6 ; TB3.2 TB3.1 ; TB3.2 21.2,69.6 ; TB3.1 22.4,78.4 ; TB3.1 17,80.5 ; TB3.1 13,78.4
MAINRLY_5V: length 347.9
  TOP w0.2: 150.12,158.5 172.5,158.5 177.9,163.9 214.4,163.9 216.25,162.05 219.55,162.05 220.2,162.7 314.3,162.7 324.4,152.6 324.4,122.99 318.61,117.2 310.61,117.2 306.2,112.79 306.2,36.66 296.5,26.96 296.5,17.5 295.62,16.62 294.43,16.62 ; 139.15,160.3 146.38,160.3 148.18,158.5 TP74.1
  TOP w0.35: IC20.18 294.43,16.62
  TOP w0.8: 139.15,160.3 R14.1
  TOP w1.7: 150.12,158.5 TP74.1
RDY: length 520
  TOP w0.2: v1(207.1,29.85) 207,30.2 207,34.6 207.37,34.97 207.37,35.61 ; 160.87,35.48 160.87,32.5 162,31.36 v1(162,29.1) ; 184.63,158.02 184.63,159.51 v1(184.25,159.9) ; 186.57,18.02 184.05,18.02 183.05,17.02 v1(182.53,17.02) 182.53,16.38 181.5,15.35 177.75,15.35 177.2,15.9 177.2,17.8 176.6,18.4 175.35,18.4 ; v1(296,29.5) 296,28.59 290.81,23.4 275.51,23.4 263.26,11.15 253.75,11.15 246.6,18.3 226.29,18.3 222.49,22.1 v1(207.2,22.1) 204.9,22.1 203.6,23.4 198.7,23.4 198.3,23.8 194,23.8 v1(193.7,23.6) 193.4,23.8 185.6,23.8 184.7,22.9 v1(183.3,22.9) 181.5,22.9 181,23.4 168.3,23.4 166.9,22 165.22,22 ; 205.13,158.02 v1(205.13,159.4) ; 195.87,35.48 195.87,34.37 194.6,33.1 v1(194.6,30.45) ; 181.87,35.48 181.87,34.63 183.1,33.4 v1(183.1,30.45) ; 175.2,18.55 175.2,19.85
  TOP w0.3: 164.73,22 162.3,22 162,22.3 v1(162,23.6)
  TOP w0.35: 186.57,18.02 IC19.7
  TOP w0.6: IC10.12 184.63,158.02 ; IC1.12 207.37,35.61 ; IC12.12 205.13,158.02 ; IC3.12 195.87,35.48 ; IC7.12 160.87,35.48 ; IC5.12 181.87,35.48
  TOP w0.8: 175.2,18.55 C107.1 175.35,18.4 ; 175.2,19.85 R134.1
  TOP w1.7: 165.22,22 TP66.1 164.73,22
  BOTTOM w0.2: v1(207.2,22.1) 207.2,23.8 207.1,23.9 v1(207.1,29.85) ; v1(193.7,23.6) 194.6,24.5 v1(194.6,30.45) ; v1(182.53,17.02) 182.15,17.4 182.15,19.6 182.53,19.98 182.53,22.12 v1(183.3,22.9) 183.3,29.76 v1(183.1,30.45) ; v1(162,29.1) v1(162,23.6) ; v1(184.25,159.9) 184.95,159.2 201.2,159.2 201.9,159.9 204.39,159.9 v1(205.13,159.4) 205.49,159.05 215.05,159.05 218.5,162.5 314.71,162.5 324.3,152.91 324.3,122.89 318.61,117.2 310.7,117.2 305.8,112.3 305.8,41.89 296,32.09 v1(296,29.5)
SIG1: length 89.6
  CONDUCTIVE2 w1: C122.1 30,90.7 ; C122.1 28.3,89 ; C122.1 30,87.3 ; C122.1 31.7,89 ; ZNR1.1 20.9,118.05 ; ZNR1.1 19.1,116.25 ; ZNR1.1 22.7,116.25 ; ZNR1.1 20.9,114.45 ; R3.2 26,110.84 ; R3.2 28,112.84 ; R3.2 30,110.84 ; R3.2 28,108.84 ; C2.1 37.8,113.75 ; C2.1 34.2,113.75 ; C2.1 36,115.55 ; C2.1 36,111.95 ; F1.2 38.85,106 ; F1.2 40.75,107.9 ; F1.2 40.75,104.1
  CONDUCTIVE2 w2: L1.4 40.7,124.5
  BOTTOM w1: C2.1 36,111.25 ; C2.1 36,116.25 ; C2.1 38.5,113.75 ; C2.1 33.5,113.75 ; ZNR1.1 19,116.25 ; ZNR1.1 20.9,118.15 ; ZNR1.1 22.8,116.25 ; ZNR1.1 20.9,114.35 ; C122.1 31.8,89 ; C122.1 30,87.2 ; C122.1 30,90.8 ; C122.1 28.2,89 ; F1.2 42.75,106 ; F1.2 40.75,108 ; F1.2 38.75,106 ; F1.2 40.75,104 ; R3.2 28,108.84 ; R3.2 30,110.84 ; R3.2 28,112.84 ; R3.2 26,110.84
  BOTTOM w1.5: L1.4 46.65,124.5 ; L1.4 41.35,124.5 ; L1.4 44,121.85 ; L1.4 44,127.15
SIG2: length 133.6
  TOP w1: ZNR1.2 21.2,123.75 ; ZNR1.2 25,123.75 ; ZNR1.2 23.1,125.65 ; ZNR1.2 23.1,121.85 ; C123.1 37,87.4 ; C123.1 37,90.8 ; C123.1 38.8,89 ; C123.1 35.2,89 ; R3.1 26,131.16 ; R3.1 28,133.16 ; R3.1 30,131.16 ; R3.1 28,129.16 ; C2.2 36,138.75 ; C2.2 36,133.75 ; C2.2 33.5,136.25 ; C2.2 38.5,136.25
  TOP w2: TB2.2 17,136.35 ; TB2.2 21.5,133.6 ; TB2.2 17,129.3 ; TB2.2 13,133.6 ; TB2.1 17,145.15 ; TB2.1 21.5,142.4 ; TB2.1 13.4,142.4 ; TB2.1 17,139.65
  TOP w2.5: L1.2 41.5,115.5
  CONDUCTIVE3 w1: ZNR1.2 23.1,125.55 ; ZNR1.2 24.9,123.75 ; ZNR1.2 23.1,121.95 ; ZNR1.2 21.3,123.75 ; C123.1 35.3,89 ; C123.1 38.7,89 ; C123.1 37,90.7 ; C2.2 37.8,136.25 ; C2.2 36,134.45 ; C2.2 36,138.05 ; C2.2 34.2,136.25 ; R3.1 26,131.16 ; R3.1 28,129.16 ; R3.1 30,131.16 ; R3.1 28,133.16
  CONDUCTIVE3 w1.5: L1.2 46.25,115.5 ; L1.2 44,117.75 ; L1.2 44,113.25 ; L1.2 41.75,115.5
  CONDUCTIVE3 w2: TB2.1 13.4,142.4 ; TB2.1 17,145.7 ; TB2.1 23.1,142.4 ; TB2.1 17,139.1 ; TB2.2 17,129.9 ; TB2.2 17,136.7 ; TB2.2 22.8,133.6 ; TB2.2 13,133.6
VDC_M: length 62.5
  TOP w0.5: Q4.D4 195.37,73.78 ; 195.37,70.9 Q4.D1 201.43,70.9
  TOP w0.7: Q4.D4 196.5,75.4 ; 200.3,75.4 200.3,73.7 ; Q4.D2 199.03,75.3 ; 197.76,73.78 197.76,75.3
  TOP w1: Q5.D 181.7,70 ; Q5.D D27.C ; Q5.D 185.65,70 ; Q5.D 183.5,72.15 ; 185.5,129.49 Q7.D
  TOP w1.4: D28.C 185.5,129.49
  BOTTOM w1: D14.C 169.54,90.6 ; Q5.D 185.3,70 ; 197.4,96.8 196.6,96 D6.A 195.46,94.4
  BOTTOM w1.5: Q7.D 184.1,127.5 ; Q7.D 186.9,127.5 ; Q7.D 185.5,129.1 ; Q7.D 185.5,125.7 ; 171.64,89 D14.C 169.54,86.9 ; 193.36,96 D6.A 195.46,97.9 ; Q5.D 183.5,72.25
  BOTTOM w2: L3.2 152.4,87 ; L3.2 152.4,78.8 ; L3.2 149.2,82.7 ; L3.2 155.4,82.7
  vias: v2(181.5,73) v2(183.5,82.5) v2(183.5,74.5) v2(185,73) v2(186.5,80.5) v2(187,84.5) v2(189.5,82.5) v2(192.5,84.5) v2(192.5,80.5) v2(195.5,82.5) v2(197.9,84.1) v2(198.5,80.5) v2(200.8,81) v2(201.5,78)
VDC_M_DCT: length 151
  TOP w0.35: v1(263.4,61.1) 263.9,60.6 263.9,60.11
  TOP w0.7: C112.2 236.1,106.8 ; C112.2 C114.2 ; C112.2 v2(233,105) C113.1 ; C113.1 236,103.2 ; C113.1 C115.1 ; C110.2 C114.2 ; C110.2 v2(220,105) C111.1 ; C110.2 v2(216.5,106.8) ; C114.2 v2(226.5,105) C115.1 ; R56.1 236.4,107.78 ; C115.1 C111.1 ; C111.1 216.5,103.2
  TOP w0.8: 263.9,60.11 R102.1
  TOP w1: R61.2 v2(238.5,105) R56.1 241.4,107.78 ; R61.2 241,102.72 ; R61.2 236.6,102.72 ; Q8.D D29.C
  CONDUCTIVE3 w0.25: C55.1 273.6,61.1 v1(263.4,61.1)
  BOTTOM w1.2: Q8.D 208.6,127.5
  BOTTOM w1.5: C55.1 282.25,73 ; C55.1 288.2,73 ; C55.1 285.5,70.4 ; C55.1 285.5,76.25 ; 207,129.25 Q8.D 207,125.25 ; C48.2 243,135.5 ; C48.2 239.75,133 ; C48.2 246.25,133 ; C48.2 243,128.9 ; C49.2 284.25,133 ; C49.2 277.75,133 ; C49.2 281,128.9 ; C49.2 281,135.5 ; C54.1 234.75,73 ; C54.1 238,76.25 ; C54.1 241.25,73 ; C54.1 238,70.3
  vias: v2(216.5,103.1) v2(217,105) v2(223,105) v2(230,105) v2(236,105) v2(240.5,105) v2(241.6,106.6) v2(241.6,103.2) v2(242.6,101.8) v2(242.8,108.2) v2(243,105) v2(244,106.8) v2(244,103.2) v2(245.8,108.2) v2(245.8,106) v2(245.8,104) v2(245.8,101.8)
VDC_N: length 228.6
  TOP w0.2: 266.87,48.12 265.7,48.12 265.1,47.52 265.1,47.2
  TOP w0.25: 266.7,51.33 266.7,50.17 ; 252.2,49.83 252.2,49.2 252.5,48.9 252.5,48.25 ; 267,48.5 267,48.9 266.7,49.2 C93.2 ; 252.2,50.17 252.2,51.33 ; 252.35,48.02 251.12,48.02 250.6,47.5 R128.1
  TOP w0.3: 252.08,50 v1(251,50) ; v1(265.4,50) 266.51,50
  TOP w0.45: 265.1,47.2 R114.1
  TOP w0.5: 170.53,66.5 Q6.D1 164.47,66.5
  TOP w0.6: 252.35,48.02 L7.2 252.5,48.25 ; 267,48.5 L6.2 266.87,48.12
  TOP w0.7: Q6.D2 168.13,70.8 ; 169.4,71.7 169.4,69.2 ; C111.2 v2(220,96) ; C111.2 216.5,97.8 ; C111.2 C115.2 ; C113.2 C115.2 ; C113.2 236,97.8 ; C113.2 v2(233,96) ; C115.2 226.5,96 ; Q6.D4 165.59,70.9 ; Q6.D3 166.87,70.9
  TOP w0.8: C99.2 252.08,50 ; C99.2 252.2,50.17 ; C99.2 252.2,49.83 ; 266.51,50 C93.2 266.7,50.17 ; R110.1 266.7,51.33 ; 252.2,51.33 R122.1
  TOP w1: R61.1 241.2,97.28 ; R61.1 236.6,97.28 ; R61.1 238.5,95.4 ; D14.A 164.46,94.5 ; D14.A 162.5,93 ; D14.A 164.46,91.2 ; D14.A 165.7,93
  CONDUCTIVE2 w0.3: 278.15,73 281.6,73 282.2,72.4 282.2,69.7 273.7,61.2 266.9,61.2 265.2,59.5 265.2,57.2 265.6,56.8 266.4,56.8 266.8,56.4 266.8,55.6 267.4,55 270.2,55 271.5,53.7 271.5,50.9 270.6,50 v1(265.4,50) ; 253.8,59 254.2,58.6 ; 254.2,58.6 254.2,56.9 256.8,54.3 258.5,54.3 258.6,54.2 258.6,53.6 259,53.2 261.3,53.2 261.8,52.7 261.8,50.6 261.2,50 v1(251,50) ; 254.2,58.6 254.2,59.2
  CONDUCTIVE2 w1: D14.A 164.46,94.9 ; D14.A 162.56,93 ; D14.A 164.46,91.1 ; D14.A 166.36,93 ; D12.A 169.54,119.3 ; D12.A 169.54,115.6 ; D12.A 171.44,117.57
  CONDUCTIVE2 w1.5: C54.2 250.65,73 ; C54.2 248,70.35 ; C54.2 245.35,73 ; C54.2 248,75.65 ; C55.2 272.85,73 ; C55.2 278.15,73 ; C55.2 275.5,75.65 ; C55.2 275.5,70.35
  CONDUCTIVE2 w2: TB5.1 313,131.9 ; TB5.1 313,137.7 ; TB5.1 307.4,135.4 ; TB5.1 317,135.4 ; TB5.2 313,124.5 ; TB5.2 313,129.9 ; TB5.2 317,126.6 ; TB5.2 307.7,126.6
  BOTTOM w2: TB5.2 313,129.35 ; TB5.2 308.5,126.6 ; TB5.2 317,126.6 ; TB5.2 313,124.5 ; TB5.1 317,135.4 ; TB5.1 313,132.65 ; TB5.1 308.5,135.4
  vias: v2(164.6,73.5) v2(164.6,71) v2(165.6,72.2) v2(166.8,73.5) v2(166.8,71) v2(167.8,72.2) v2(169.1,73.5) v2(169.1,71) v2(170.2,72.2) v2(171.2,73.5) v2(171.2,70.9) v2(216.5,97) v2(218.5,93.5) v2(221.5,93.5) v2(225,93.5) v2(226.53,96.06) v2(228,93.5) v2(231.5,93.5) v2(234.8,94.6) v2(237.4,95.2) v2(242.4,97.9) v2(242.4,95.8)
VDC_P: length 156.8
  TOP w0.2: 260.6,56.95 260.6,57.9 v1(260.2,58.3)
  TOP w0.7: R56.2 236.2,113.22 ; C110.1 216.5,112.2 ; C110.1 v2(220,114) ; C110.1 C114.1 ; v2(226.5,114) C114.1 ; C114.1 C112.1 ; C112.1 v2(233,114) ; C112.1 236,112.2
  TOP w0.8: 260.6,56.95 R117.1
  TOP w1: v2(238.5,115.5) R56.2 240.9,113.22 ; D7.C 169.54,128.43 ; D7.C 168.3,126.43 ; D7.C 169.54,124.7 ; D7.C 171.54,126.43 ; Q3.D 210.35,70 ; Q3.D 214.65,70 ; Q3.D D26.C ; Q3.D 212.5,72.15 ; D6.C 199.3,92 ; D6.C 202.54,92 ; D6.C 200.54,93.8 ; D6.C 200.54,90
  TOP w2: TB4.1 311,149.3 ; TB4.1 305.9,152.4 ; TB4.1 311,155.3 ; TB4.1 314.6,152.4 ; TB4.2 306.3,143.6 ; TB4.2 311,146.6 ; TB4.2 315.5,143.6
  CONDUCTIVE3 w1: D6.C 200.54,93.9 ; D6.C 202.44,92 ; D6.C 198.64,92 ; D6.C 200.54,90.1 ; D7.C 171.44,126.43 ; D7.C 167.64,126.43 ; D7.C 169.54,127.7 ; D7.C 169.54,124.53
  CONDUCTIVE3 w1.5: C49.1 283.65,143 ; C49.1 281,145.65 ; C49.1 281,140.35 ; C49.1 278.35,143 ; C48.1 243,145.65 ; C48.1 243,140.35 ; C48.1 240.35,143 ; C48.1 245.65,143 ; 211.2,70 Q3.D ; Q3.D 214.4,70 ; Q3.D 212.5,68.4 ; Q3.D 212.5,71.9
  CONDUCTIVE3 w2: TB4.1 311,149.1 ; TB4.1 306.1,152.4 ; TB4.1 314.6,152.4 ; TB4.1 311,155.1 ; TB4.2 316.4,143.6 ; TB4.2 305.3,143.6 ; TB4.2 311,141.3 ; TB4.2 311,146.9
  vias: v2(216.5,113) v2(218.5,116.5) v2(221.5,116.5) v2(225,116.5) v2(228,116.5) v2(231.5,116.5) v2(234.5,116.5) v2(242.05,114.79) v2(244.2,114)
VREF: length 20.3
  TOP w0.2: v1(259.85,19.1) 259.85,20.07
  TOP w0.3: C78.1 249,26.9 248.43,27.47 248.43,28.49
  TOP w0.35: 259.85,20.07 IC17.10
  TOP w0.5: IC14.5 247.6,26.45 247.75,26.3 248.72,26.3 ; 249.28,26.3 v1(250.4,26.3)
  TOP w0.8: 249.28,26.3 C78.1 248.72,26.3
  TOP w1.7: 248.43,28.49 TP51.1
  BOTTOM w0.25: v1(250.4,26.3) 252.65,26.3 v1(259.85,19.1)
VREF_IN: length 196.1
  TOP w0.2: 258,19.3 256.2,19.3 253.4,22.1 229.8,22.1 224,27.9 156.7,27.9 151.6,22.8 134.68,22.8 129.68,27.8 v1(120,27.8) ; 258,19.3 258.2,19.3 ; 258,19.3 258.2,19.1 ; 258.2,19.3 258.2,19.1 ; 258.2,19.3 258.4,19.3 ; 258.4,19.3 258.2,19.1 ; 258.4,19.3 258.46,19.3 ; 258.2,19.1 258.2,18.27 ; 258.46,19.3 258.46,20.04 ; 258.46,19.3 259,19.3 259.2,19.5 259.2,20.07
  TOP w0.25: R81.2 100.15,55.8 v1(100.8,55.9) 100.8,55.22
  TOP w0.3: 256.79,18.2 258.01,18.2
  TOP w0.35: IC17.9 259.2,20.07
  TOP w0.45: 100.8,55.22 C73.2
  TOP w0.5: 258.46,20.04 IC17.8
  TOP w0.8: 258.01,18.2 R99.1 258.2,18.27 ; C89.1 256.79,18.2
  BOTTOM w0.25: v1(120,27.8) 119,27.8 117,29.8 117,32.25 114.45,34.8 109.75,34.8 98.65,45.9 98.65,53.75 v1(100.8,55.9)
N18160714: length 17.5
  TOP w0.2: 209.7,56.55 209.7,55.3 209.5,55.1 208.86,55.1
  TOP w0.3: 211.18,46.56 211.18,57.52 210.4,58.3 R18.1
  TOP w0.4: 209.7,58.07 209.7,56.93
  TOP w0.5: 208.82,55.1 208.86,55.1
  TOP w0.6: 211.18,46.56 IC1.2
  TOP w0.8: 209.7,56.55 C20.1 209.7,56.93 ; R18.1 209.7,58.07
N18160718: length 2.4
  TOP w0.5: 208.1,60.02 208.1,58.58
  TOP w0.8: 208.1,58.58 R18.2
  TOP w1.4: D4.A 208.1,60.02
N18160720: length 2.7
  TOP w1: 212.5,62.89 212.5,61.21
  TOP w1.4: 212.5,61.21 D4.C ; D26.A 212.5,62.89
N18160890: length 10.3
  TOP w0.6: IC2.8 227.6,46.3
  TOP w0.7: C18.1 228.5,46.4 228.4,46.3 C19.1
  TOP w0.8: C18.1 231.88,46.4 233.6,48.12 PS3.7
N18160918: length 5.2
  TOP w0.2: 204.82,35.49 204.82,34.64 203.3,33.12 203.3,31.85
  TOP w0.6: IC1.10 204.82,35.49
  TOP w0.8: 203.3,31.85 R20.1
N18160932: length 30.6
  TOP w0.3: 217.4,61.01 217.4,59.79
  TOP w0.5: 217.4,61.48 217.4,62.8 Q3.G ; 217.4,59.33 217.4,58.1 ; 217,55.77 217,57.4
  TOP w0.6: IC1.7 v2(204.82,47.9)
  TOP w0.8: 217.4,61.01 C22.1 217.4,61.48 ; R21.2 217,55.77 ; 217.4,59.79 R26.2 217.4,59.33
  TOP w0.9: Q3.G D5.A
  BOTTOM w0.5: CN1.S 219.65,61.95 ; CN1.S 217.85,60.5 ; CN1.S 219.65,59.05 ; TP18.1 221,69.1 ; TP18.1 219.4,67 ; TP18.1 221,65.05
  BOTTOM w1: Q3.G 217.95,62.25 ; Q3.G 220.2,64.5 ; Q3.G 217.95,66.75
  vias: v2(216.5,57.4) v2(217.6,58) v2(217.6,56.8)
N18160934: length 7.2
  TOP w0.25: 226.34,49.26 226.34,49.84 226.8,50.3 228.3,50.3 228.8,49.8 R25.1
  TOP w0.3: 226.34,47.65 226.34,47.23 226,46.9 R27.2
  TOP w0.6: 226.34,47.65 226.34,49.26
N18160956: length 8.8
  TOP w0.5: 215.6,53.7 R21.1 R23.1 219.6,52.55
  TOP w0.6: R21.1 217,52.3 ; IC1.6 206.09,47.05 206.19,47.14 206.19,47.34 v2(206.4,47.9)
  vias: v2(216.95,52.3) v2(218.3,52.3) v2(219.7,52.3)
N18161146: length 1.6
  TOP w0.25: 229.67,53 230.93,53
  TOP w0.8: R22.1 229.67,53 ; 230.93,53 R24.1
N18161536: length 5.4
  TOP w0.2: 193.32,35.55 193.32,34.77 191.2,32.65 191.2,31.85
  TOP w0.6: IC3.10 193.32,35.55
  TOP w0.8: 191.2,31.85 R29.1
N18161570: length 26
  TOP w0.5: C26.2 R30.1 ; C26.2 200.6,66.15 ; C26.2 201.75,65 ; R30.1 200.6,62.35 ; R30.1 201.75,63.5 ; 193.32,46.65 v2(193.32,47.6) ; Q4.G 201.43,68.03
  TOP w0.6: IC3.7 193.32,46.65
  TOP w0.7: Q4.G 200.31,66.6
  TOP w0.8: R31.2 200,60.45
  TOP w1: 203.8,67.4 D9.A 201.9,65.4
  BOTTOM w0.4: v2(201.25,62.05) 203.3,62.05 CN2.S
  BOTTOM w0.5: TP22.1 200.3,56.7 ; TP22.1 200.3,60.45 ; TP22.1 198.7,58.5
  vias: v2(199.45,62.1) v2(200.35,60.95)
N18161621: length 8.1
  TOP w0.5: 203,55.75 R32.1 201.6,56.9 ; R31.1 198.85,56.9 ; R31.1 200,55.75 ; R31.1 201.4,56.9 ; v2(194.8,47.6) 194.59,47.04 IC3.6
  vias: v2(199.55,55.05) v2(200.9,55.05) v2(202.25,55.05)
N18162020: length 19
  TOP w0.2: 180.5,56.45 180.5,55.3 180.1,54.9 D13.C
  TOP w0.3: 185.68,46.56 185.68,50.52 181.6,54.6 181.6,57.8 181.2,58.2 R37.1 ; 180.5,56.79 180.5,58.01
  TOP w0.6: 185.68,46.56 IC5.2
  TOP w0.8: 180.5,56.79 C39.1 180.5,56.45 ; 180.5,58.01 R37.1
N18162024: length 2.7
  TOP w0.3: 178.9,60.31 178.9,58.39
  TOP w0.8: 178.9,58.39 R37.2
  TOP w1.4: D10.A 178.9,60.31
N18162026: length 2.5
  TOP w1: D27.A 183.33,61.25
  TOP w1.4: 183.33,61.25 D10.C
N18162137: length 4.7
  TOP w0.2: 179.6,31.85 179.6,32.77 179.32,33.05 179.32,35.48
  TOP w0.6: IC5.10 179.32,35.48
  TOP w0.8: 179.6,31.85 R39.1
N18162177: length 27.5
  TOP w0.4: C34.1 R42.2 188.2,59.8 188.2,58.6
  TOP w0.5: C34.1 188.1,62.45
  TOP w0.6: IC5.7 v2(179.32,47.6)
  TOP w0.8: R40.2 v2(188,56.5)
  TOP w1: 188.35,62.45 Q5.G 190.6,62.85 190.6,62.01
  TOP w1.4: 190.6,62.01 D11.A
  BOTTOM w0.5: CN3.S 188.6,59.85 189,60.25 ; TP26.1 188.7,57.8 ; TP26.1 190.3,55.85 ; TP26.1 190.3,59.75
  BOTTOM w1.5: 188.95,62.25 Q5.G 187.2,64.5
  vias: v2(187.6,57.6) v2(188.1,58.7)
N18162199: length 9.1
  TOP w0.5: R40.1 188,52.15 ; R40.1 R41.1 ; R40.1 186.85,53.3 ; R41.1 191.75,53.3 ; R41.1 190.6,52.15
  TOP w0.6: IC5.6 180.59,46.72 180.61,46.73 v2(180.9,47.6)
  vias: v2(187.6,52) v2(189.4,52) v2(191.2,52)
N18162278: length 2.3
  TOP w0.8: R41.2 D11.C
N18162297: length 18
  TOP w0.5: 150.87,57.49 144.8,57.49 144.4,57.09 144.4,56.48 ; 144.23,56.2 143.1,56.2 142.6,55.7 142.6,53.96
  TOP w0.6: IC6.8 150.87,57.49
  TOP w0.8: 144.23,56.2 C37.1 144.4,56.48
  TOP w1: PS5.7 142.59,52.35
  TOP w1.2: 142.6,53.96 C36.1 142.59,52.35
N18162335: length 12.8
  TOP w0.3: 152.41,58.77 153,58.77 153.5,58.27 153.5,55.49 ; 152.41,63.2 150.8,63.2 150.2,62.6 150.2,59 150.44,58.77 150.95,58.77
  TOP w0.6: 152.41,58.77 IC6.7 150.95,58.77
  TOP w0.8: R46.2 152.41,63.2 ; 153.5,55.49 R45.1
N18162845: length 4.4
  TOP w0.2: R48.1 158.32,32.7 158.32,35.48
  TOP w0.6: IC7.10 158.32,35.48
N18162894: length 23.6
  TOP w0.5: R49.1 171,59.4 ; R49.1 C43.2 ; R49.1 169.6,58 ; R50.2 170.6,57 ; C43.2 169.6,62 ; C43.2 171,61
  TOP w0.6: IC7.7 v2(158.32,47.6)
  TOP w0.7: Q6.G 169.41,62.2
  TOP w1: 171.1,61.8 D15.A 173,63.4
  BOTTOM w0.5: 170,58.2 TP31.1 171.6,61 ; 172,62.05 175.38,62.05
  BOTTOM w1.4: 175.38,62.05 CN4.S
  vias: v2(169.8,57.3) v2(171,58.2) v2(171,56.4)
N18162939: length 9
  TOP w0.5: R50.1 169.45,53.3 ; R50.1 170.6,52 ; R50.1 R51.1 173.4,51.5
  TOP w0.6: v2(159.9,47.6) 159.61,46.73 159.59,46.72 IC7.6
  vias: v2(170.1,51.9) v2(172,51.9) v2(173.7,51.9)
N18165597: length 7.5
  TOP w0.2: 270,47.16 270,47.42 269.3,48.12 268.13,48.12
  TOP w0.25: 268,48.5 268,49 268.3,49.3 C93.1
  TOP w0.35: 268.51,50 269.49,50 ; 268.3,51.29 268.3,50.21
  TOP w0.45: 270,47.16 R101.1
  TOP w0.6: 268,48.5 L6.1 268.13,48.12
  TOP w0.8: 268.3,50.21 C93.1 268.51,50 ; R110.2 268.3,51.29 ; 269.49,50 R106.2
N18165601: length 18.3
  TOP w0.2: L6.4 268.98,45.1 R101.2 ; 277.77,49 275,49 271.8,45.8 270.6,45.8 D24.A
  TOP w0.4: 270.05,44.47 270.05,43.63 IC16.2 ; 268,44.84 268,43.2 268.77,42.43
  TOP w0.6: L6.4 268,44.84
  TOP w0.8: 270.05,44.47 D24.A
  TOP w1.5: 268.77,42.43 IC16.2
  TOP w1.7: 277.77,49 TP60.1
N18165829: length 8.3
  TOP w0.2: R114.2 266.1,45.12 L6.3
  TOP w0.4: R111.1 264.51,44.07 IC16.3 ; 266.23,42.43 267,43.2 267,44.84
  TOP w0.6: L6.3 267,44.84
  TOP w1.5: 266.23,42.43 IC16.3
N18166226: length 7.8
  TOP w0.25: 253.5,48.4 253.5,48.85 253.8,49.15 C99.1 ; 253.65,48.02 254.88,48.02 255.4,47.5 R115.1
  TOP w0.3: 255.21,50 253.99,50 ; 253.8,51.31 253.8,50.19
  TOP w0.6: 253.5,48.4 L7.1 253.65,48.02
  TOP w0.8: R122.2 253.8,51.31 ; 253.99,50 C99.1 253.8,50.19 ; R125.2 255.21,50
N18166230: length 15.8
  TOP w0.25: 255.4,45.98 255.4,45.4 255,45 254.2,45 L7.4
  TOP w0.3: 256.85,45.17 256.85,46.3 257.05,46.5 261.73,46.5
  TOP w0.4: 253.5,44.53 253.5,43.4 253.74,43.08 IC18.2 255.8,43.88 D25.A
  TOP w0.45: R115.2 255.4,45.98
  TOP w0.6: L7.4 253.5,44.53
  TOP w0.8: D25.A 256.85,45.17
  TOP w1.7: 261.73,46.5 TP61.1
N18166390: length 1.7
  TOP w0.25: 259,56.73 259,55.7 R118.1
  TOP w0.8: R117.2 259,56.73
N18166392: length 1.8
  TOP w0.25: R118.2 259.3,53.2 R119.1
N18166394: length 1.6
  TOP w0.35: 261.8,52.99 261.8,51.81
  TOP w0.8: 261.8,51.81 R120.1 ; R119.2 261.8,52.99
N18166396: length 1.6
  TOP w0.35: 261.59,50 260.41,50
  TOP w0.8: R120.2 261.59,50 ; 260.41,50 R121.1
N18166398: length 1.6
  TOP w0.3: 258.41,50 257.19,50
  TOP w0.8: R121.2 258.41,50 ; 257.19,50 R125.1
N18166467: length 9.4
  TOP w0.25: 250.6,45.98 250.6,45.4 251,45 251.9,45 L7.3
  TOP w0.3: R127.1 249.7,44.5 IC18.3
  TOP w0.4: 252.5,44.53 252.5,43.4 252.26,43.08 IC18.3
  TOP w0.45: R128.2 250.6,45.98
  TOP w0.6: L7.3 252.5,44.53
N18172539: length 1.9
  TOP w0.5: 111.58,29 112.92,29
  TOP w0.8: R85.2 111.58,29 ; 112.92,29 LED3.A
N18174546: length 12.7
  TOP w0.6: C52.1 152.36,147.3 152.56,147.09 IC9.8
  TOP w0.7: 146.96,148.9 145.7,148.9 145,149.6 PS7.7 ; 148.85,148.9 150.5,148.9 151.5,147.9 C52.1
  TOP w1.2: 146.96,148.9 C51.1 148.85,148.9
N18174588: length 6.6
  TOP w0.3: 154.81,148.37 155.63,148.37 156.3,147.7 156.3,145.39
  TOP w0.5: R60.2 156.22,145.2
  TOP w0.6: IC9.7 154.81,148.37
  TOP w0.8: 156.3,145.39 R59.1 156.22,145.2
N18174803: length 24
  TOP w0.5: C68.2 201.2,135 201.31,134.36 Q8.G ; 201.2,137.32 v2(201.2,138.5) ; R75.2 201.1,140.65
  TOP w0.6: C68.2 R74.1 ; v2(208.06,145.76) 207.68,146.15 IC12.7
  TOP w0.8: R74.1 201.2,137.32
  TOP w1: D19.A 199,134.7 200.1,133.6 Q8.G
  BOTTOM w0.5: CN6.S 198.15,133 Q8.G 199,130.45 199,129.35
  BOTTOM w1.7: 199,129.35 TP42.1
  vias: v2(201.1,140.3) v2(202.4,139.2)
N18174813: length 20.7
  TOP w0.5: Q7.G 180,134.7 180.1,134.8 180.1,135.43 ; R67.2 180.1,138.45 ; R65.2 180.2,140.65 ; 180.1,135.97 180.1,137.03
  TOP w0.6: IC10.7 v2(187.2,145.9)
  TOP w0.8: 180.1,137.03 R67.2 ; 180.1,135.43 C59.1 180.1,135.97
  TOP w1: Q7.G 178.5,133.8 177.8,134.5 D17.A
  BOTTOM w1: Q7.G 177.7,133 177.65,133.05 176.03,133.05 ; 175.5,129.56 175.5,132.17
  BOTTOM w1.4: 175.5,132.17 CN5.S 176.03,133.05
  BOTTOM w1.7: TP36.1 175.5,129.56
  vias: v2(180.3,140.4) v2(180.3,139.1) v2(181.4,139.8)
N18174987: length 11.5
  TOP w0.25: 183.86,142.8 184.47,142.8
  TOP w0.3: 184.6,142.8 184.6,143.22 184.2,143.62 182.07,143.62 180.82,144.88 180.82,146.94 ; 184.6,142.8 184.6,141.59 ; 184.6,142.8 184.47,142.8 ; 184.6,140.09 184.6,141.21
  TOP w0.5: 183.72,142.8 183.86,142.8
  TOP w0.6: IC10.2 180.82,146.94
  TOP w0.8: R64.1 184.6,140.09 ; 184.6,141.59 C60.1 184.6,141.21
N18174991: length 2.4
  TOP w0.5: 187.95,140.7 187.2,140.7 186.62,140.12 R64.2
  TOP w1.4: 187.95,140.7 D16.A
N18175001: length 4
  TOP w1: 188.3,136.14 188.3,135.7 186.8,134.2 185.85,134.2
  TOP w1.4: D28.A 185.85,134.2 ; 188.3,136.14 D16.C
N18175042: length 3.1
  TOP w0.2: 187.5,160.05 187.5,159.32 187.18,159 187.18,158.02
  TOP w0.6: IC10.10 187.18,158.02
  TOP w0.8: 187.5,160.05 R63.1
N18175086: length 10.6
  TOP w0.5: R65.1 R66.1 177.8,144 ; 180.2,143.88 180.2,144.4 v2(179.8,144.8) v2(178.6,144.8) ; v2(178.6,144.8) 177.8,144 ; v2(178.6,144.8) v2(177.4,144.8) 177.8,144.4 177.8,144
  TOP w0.6: IC10.6 185.91,146.46 v2(185.7,145.9)
  TOP w0.8: 180.2,143.88 R65.1
N18175142: length 2.1
  TOP w0.5: 177.8,139.91 177.8,141.53
  TOP w0.8: 177.8,141.53 R66.2
  TOP w1.4: D17.C 177.8,139.91
N18175684: length 2.6
  TOP w0.2: 207.68,157.89 207.68,158.6 208,158.93 208,159.55
  TOP w0.6: IC12.10 207.68,157.89
  TOP w0.8: 208,159.55 R73.1
N18175726: length 8.1
  TOP w0.5: R76.1 197.8,143.6 ; R76.1 199,144.75 ; R76.1 R75.1 201.1,144.4 200.7,144.8 200.45,144.8
  TOP w0.6: IC12.6 v2(206.41,145.7)
  vias: v2(198,144.8) v2(199.2,144.8) v2(200.5,144.7)
N18175764: length 2.2
  TOP w0.5: 199,139.86 199,141.53
  TOP w0.8: 199,141.53 R76.2
  TOP w1.4: D19.C 199,139.86
N18175788: length 12.4
  TOP w0.25: 205.06,142.5 205.67,142.5
  TOP w0.3: 205.8,142.5 205.8,142.9 205.2,143.5 203.1,143.5 201.32,145.28 201.32,146.94 ; 205.8,142.5 205.67,142.5 ; 205.8,142.5 205.8,141.19 ; 206.2,139.57 206.2,140.6 C69.1
  TOP w0.5: D20.C 205.06,142.5
  TOP w0.6: 201.32,146.94 IC12.2
  TOP w0.8: 205.8,141.19 C69.1 ; R77.1 206.2,139.57
